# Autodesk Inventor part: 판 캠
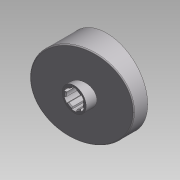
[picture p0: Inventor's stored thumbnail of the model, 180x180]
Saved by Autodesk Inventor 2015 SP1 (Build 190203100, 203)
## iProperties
Company: 한국ATC센터
Created: 2014-07
Part Number: 판 캠
Document SubType Name: 모델링
Designer: KYOUNG IL JANG
Material: 강철
Mass: 681.587 g
Surface Area: 331.303 cm^2
Volume: 86.8264 cm^3
Density: 7.85 g/cm^3
Appearance: 알루미늄 - 평지
변환 표준: STEP AP214IS
파일 이름: C:\Users\SeoGD\Desktop\?쒗뿕\??stp
전처리기: Build: 253, Release: 2010 SP1 - Date: Wed 07/29/2009
전송 단위: 밀리미터
불확실성: 0.01
Author: KYOUNG IL JANG
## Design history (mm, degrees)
node "작업 평면4"
sketch "스케치1"
  geometry: C1 r 44.5 at (0, 0); 1 further point
  constraints: 1 centre point, 1 coincident
  dimensions: "d25" = 89 diameter of C1
extrude "돌출1" new body sketch "스케치1" distance "d1" = 40; taper "d2" = 0 deg
sketch "스케치2"
  geometry: L1 (-44.5, 15)-(44.5, 38.847); L2 (-44.5, 0)-(-44.5, 40) reference; L3 (-44.5, 40)-(44.5, 40) reference; L4 (44.5, 0)-(44.5, 40) reference; 1 further point
  constraints: 2 end point, 2 point on line
  dimensions: "d26" = 15 distance of L2.start L1.start; "d27" = 75 deg angle of L1 L2
extrude "돌출2" cut sketch "스케치2" stored distance "d5" = 40; taper "d6" = 0 deg
node "작업 평면1"
sketch "스케치3"
  geometry: C1 r 13 at (0, 0); 1 further point
  constraints: 1 centre point, 1 coincident
  dimensions: "d9" = 26 diameter of C1
extrude "돌출3" join sketch "스케치3" distance "d10" = 38; taper "d11" = 0 deg
hole "구멍1" diameter "d14" = 18; stored, may be unused: countersink angle "d18" = 90 deg, drill point angle "d20" = 118 deg; dims "d12" = 10, "d13" = 10, "d15" = 6, "d16" = 4, "d17" = 2, "d19" = 8
feature "쉘2" dims "d29" = 5
sketch "스케치6"
  geometry: C1 r 17.5 at (0, 0); C2 r 14 at (0, 0) reference; 1 further point
  constraints: 1 centre point, 1 coincident
  dimensions: "d28" = 35 diameter of C1
extrude "돌출4" join sketch "스케치6" stored distance "d30" = 38; taper "d31" = 0 deg
fillet "모깎기1" dims "d32" = 3
chamfer "모따기1" distance "d21" = 1; stored, may be unused: second distance "d22" = 2, angle "d23" = 45 deg
sketch "스케치7"
  geometry: L1 (-12.374, 12.374)-(-27.931, 27.931); A1 r 39.5 centre (0, 0) between (-27.931, 27.931) and (0, 39.5) reference; 2 further points
  constraints: 2 end point, 2 point on circle, 1 point on line, 1 vertical alignment, 2 other
  dimensions: "d33" = 45 deg dimension on point (0, 0) L1.start A1.end
feature "리브1" sketch "스케치7" dims "d34" = 5, "d35" = 1, "d36" = 0
fillet "모깎기2" dims "d37" = 3
sketch "스케치8"
  geometry: L1 (2.5, 10.712)-(2.5, 8.646); L2 (-2.5, 10.712)-(-2.5, 8.646); A1 r 11 centre (0, 0) between (2.5, 10.712) and (-2.5, 10.712); A2 r 9 centre (0, 0) between (2.5, 8.646) and (-2.5, 8.646) reference; 1 further point
  constraints: 4 end point, 4 point on circle, 2 parallel, 1 centre point, 1 coincident, 1 vertical
  dimensions: "d41" = 22 diameter of A1; "d42" = 5 distance between parallel lines of L1 L2
extrude "돌출5" cut sketch "스케치8" stored distance "d43" = 38; taper "d44" = 0 deg
fillet "모깎기3" dims "d48" = 1
node "솔리드1"
node "솔리드 본체"
node "곡면 본체"
pattern_circular "원형 패턴1" dims angle "d39" = 360 deg
pattern_circular "원형 패턴2" dims angle "d46" = 360 deg
node "솔리드2"
